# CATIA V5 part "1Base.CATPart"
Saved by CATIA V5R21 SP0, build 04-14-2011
Part number: Base
Bounding box of the stored display mesh (mm): x -51.856 to 51.856, y -32.317 to 57.5, z 0 to 12
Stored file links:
  C:\Users\Administrator\Desktop\arm\Arm_Detailed_Design_Assembly_Manu\1Base.CATPart
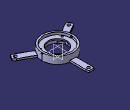
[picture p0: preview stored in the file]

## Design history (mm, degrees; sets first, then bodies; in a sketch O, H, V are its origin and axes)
Body1 (main body)
  Sketch1 on xy-plane, origin (0, 0, 0), H (1, 0, 0), V (0, 1, 0)
    circle A1 centre (0, 0) radius 26.5
    radius A1 = 26.5
  Pad1: profile Sketch1, direction (0, 0, 1), length 12
  Sketch2 on end face of Pad1, origin (0, 0, 12), H (1, 0, 0), V (0, 1, 0)
    circle A1 centre (0, 0) radius 23.5
    radius A1 = 23.5
  Pocket1: profile Sketch2, direction (0, 0, -1), up to start face of Pad1, offset -8
  Sketch3 on end face of Pocket1, origin (0, 0, 8), H (1, 0, 0), V (0, 1, 0)
    circle A1 centre (0, 0) radius 17.5
    radius A1 = 17.5
  Pocket2: profile Sketch3, direction (0, 0, -1), through (limit type 3)
  Sketch4 on end face of Pocket1, origin (0, 0, 8), H (1, 0, 0), V (0, 1, 0)
    circle A1 centre (0, 21) radius 1.5
    point P1 (0, 21)
    circle A2 centre (-18.1865, -10.5) radius 1.5
    circle A3 centre (18.1865, -10.5) radius 1.5
    radius A1 = 1.5
    distance P1 H = 21
    coincidence: P1 V
  Pocket3: profile Sketch4, direction (0, 0, -1), length 1.5
  Sketch5 on end face of Pocket3, origin (0, 0, 6.5), H (1, 0, 0), V (0, 1, 0)
    circle A1 centre (0, 21) radius 1.5
    point P1 (0, 21)
    circle A2 centre (-18.1865, -10.5) radius 1.5
    circle A3 centre (18.1865, -10.5) radius 1.5
    radius A1 = 1.5
    distance P1 H = 21
    coincidence: P1 V
  Pocket4: profile Sketch5, direction (0, 0, -1), through (limit type 3)
  Sketch6 on start face of Pad1, origin (0, 0, 0), H (1, 0, 0), V (0, -1, 0)
    line L1 (-5, -13.8154) -> (5, -13.8154)
    line L2 (5, -13.8154) -> (5, -28.4504)
    line L3 (5, -28.4504) -> (-5, -28.4504)
    line L4 (-5, -28.4504) -> (-5, -13.8154)
    line L5 (22.1387, 18.5553) -> (27.1387, 9.8951)
    line L6 (9.4645, 11.2378) -> (22.1387, 18.5553)
    line L7 (27.1387, 9.8951) -> (14.4645, 2.5776)
    line L8 (14.4645, 2.5776) -> (9.4645, 11.2378)
    line L9 (-27.1387, 9.8951) -> (-22.1387, 18.5553)
    line L10 (-14.4645, 2.5776) -> (-27.1387, 9.8951)
    line L11 (-22.1387, 18.5553) -> (-9.4645, 11.2378)
    line L12 (-9.4645, 11.2378) -> (-14.4645, 2.5776)
    distance L2 V = 5
    distance V L4 = 5
    horizontal: L1 H, L3 H
    vertical: L2 V, L4 V
  Pocket5: profile Sketch6, direction (0, 0, 1), length 3
  Sketch7 on yz-plane, origin (0, 0, 0), H (0, 1, 0), V (0, 0, 1)
    circle A1 centre (0, 10) radius 1.25
    point P1 (0, 10)
    reference projected line E1 (-26.5, 12) -> (26.5, 12) from edge [face of Pad1 from Sketch1.A1 | end face of Pad1]
    radius A1 = 1.25
    distance P1 E1 = 2
    coincidence: P1 V
  Pocket6: profile Sketch7, direction (-1, 0, 0), length 40, mirrored extent
  Sketch8 on end face of Pocket1, origin (0, 0, 8), H (1, 0, 0), V (0, 1, 0)
    circle A1 centre (0, 0) radius 16
    circle A2 centre (0, 0) radius 17.5
    reference projected circle E1 centre (0, 0) radius 17.5 from edge [end face of Pocket1 | face of Pocket2 from Sketch3.A1]
    radius A1 = 16
    coincidence: A2 E1
  Pad2: profile Sketch8, direction (0, 0, -1), length 2
Body2
  Sketch9, origin (0, 0, 3), H (-0.5, -0.866, 0), V (-0.866, 0.5, 0)
    line L1 (-5, -17.5) -> (5, -17.5)
    line L2 (5, -17.5) -> (5, -52.5)
    point P2 (5, -52.5)
    line L3 (5, -52.5) -> (4.1184, -57.5)
    line L4 (4.1184, -57.5) -> (-4.1184, -57.5)
    line L5 (-4.1184, -57.5) -> (-5, -52.5)
    point P5 (-5, -52.5)
    line L6 (-5, -52.5) -> (-5, -17.5)
    circle A1 centre (0, -52.5) radius 2.5
    point P7 (0, -52.5)
    circle A2 centre (0, -21) radius 1.5
    point P8 (0, -21)
    angle L5 L6 = 170
    angle L3 L2 = 170
    distance L1 L4 = 40
    distance P2 L1 = 35
    distance P5 L1 = 35
    radius A1 = 2.5
    distance P7 L4 = 5
    horizontal: L1 H, L4 H
    vertical: L2 V, L6 V
    coincidence: P7 V, P8 V
  Sketch10, origin (0, 0, 3), H (-0.5, 0.866, 0), V (0.866, 0.5, 0)
    line L1 (-5, -17.5) -> (5, -17.5)
    line L2 (5, -17.5) -> (5, -52.5)
    point P2 (5, -52.5)
    line L3 (5, -52.5) -> (4.1184, -57.5)
    line L4 (4.1184, -57.5) -> (-4.1184, -57.5)
    line L5 (-4.1184, -57.5) -> (-5, -52.5)
    point P5 (-5, -52.5)
    line L6 (-5, -52.5) -> (-5, -17.5)
    circle A1 centre (0, -52.5) radius 2.5
    point P7 (0, -52.5)
    circle A2 centre (0, -21) radius 1.5
    point P8 (0, -21)
    angle L5 L6 = 170
    angle L3 L2 = 170
    distance L1 L4 = 40
    distance P2 L1 = 35
    distance P5 L1 = 35
    radius A1 = 2.5
    distance P7 L4 = 5
    horizontal: L1 H, L4 H
    vertical: L2 V, L6 V
    coincidence: P7 V, P8 V
  Sketch11 on end face of Pocket5, origin (0, 0, 3), H (1, 0, 0), V (0, -1, 0)
    line L1 (-5, -17.5) -> (5, -17.5)
    line L2 (5, -17.5) -> (5, -52.5)
    point P2 (5, -52.5)
    line L3 (5, -52.5) -> (4.1184, -57.5)
    line L4 (4.1184, -57.5) -> (-4.1184, -57.5)
    line L5 (-4.1184, -57.5) -> (-5, -52.5)
    point P5 (-5, -52.5)
    line L6 (-5, -52.5) -> (-5, -17.5)
    reference projected line E1 (-5, -13.8154) -> (-5, -28.4504) from edge [end face of Pocket5 | face of Pocket5 from Sketch6.L4]
    reference projected line E2 (5, -28.4504) -> (5, -13.8154) from edge [end face of Pocket5 | face of Pocket5 from Sketch6.L2]
    reference projected arc E3 centre (0, 0) radius 17.5 from (-12.0237, 12.7154) to (-17.0237, 4.0551) ccw from edge [end face of Pocket5 | face of Pocket2 from Sketch3.A1]
    circle A1 centre (0, -52.5) radius 2.5
    point P7 (0, -52.5)
    circle A2 centre (0, -21) radius 1.5
    point P8 (0, -21)
    reference projected circle E6 centre (0, -21) radius 1.5 from edge [end face of Pocket5 | face of Pocket4 from Sketch5.A1]
    angle L5 L6 = 170
    angle L3 L2 = 170
    distance L1 L4 = 40
    distance P2 L1 = 35
    distance P5 L1 = 35
    radius A1 = 2.5
    distance P7 L4 = 5
    horizontal: L1 H, L4 H
    vertical: L2 V, L6 V
    coincidence: L6 E1, L2 E2, P7 V, P8 V, A2 E6
    tangency: L1 E3
  Pad3: profile Sketch11, direction (0, 0, -1), length 3
  Pad4: profile Sketch10, direction (0, 0, -1), length 3
  Pad5: profile Sketch9, direction (0, 0, -1), length 3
